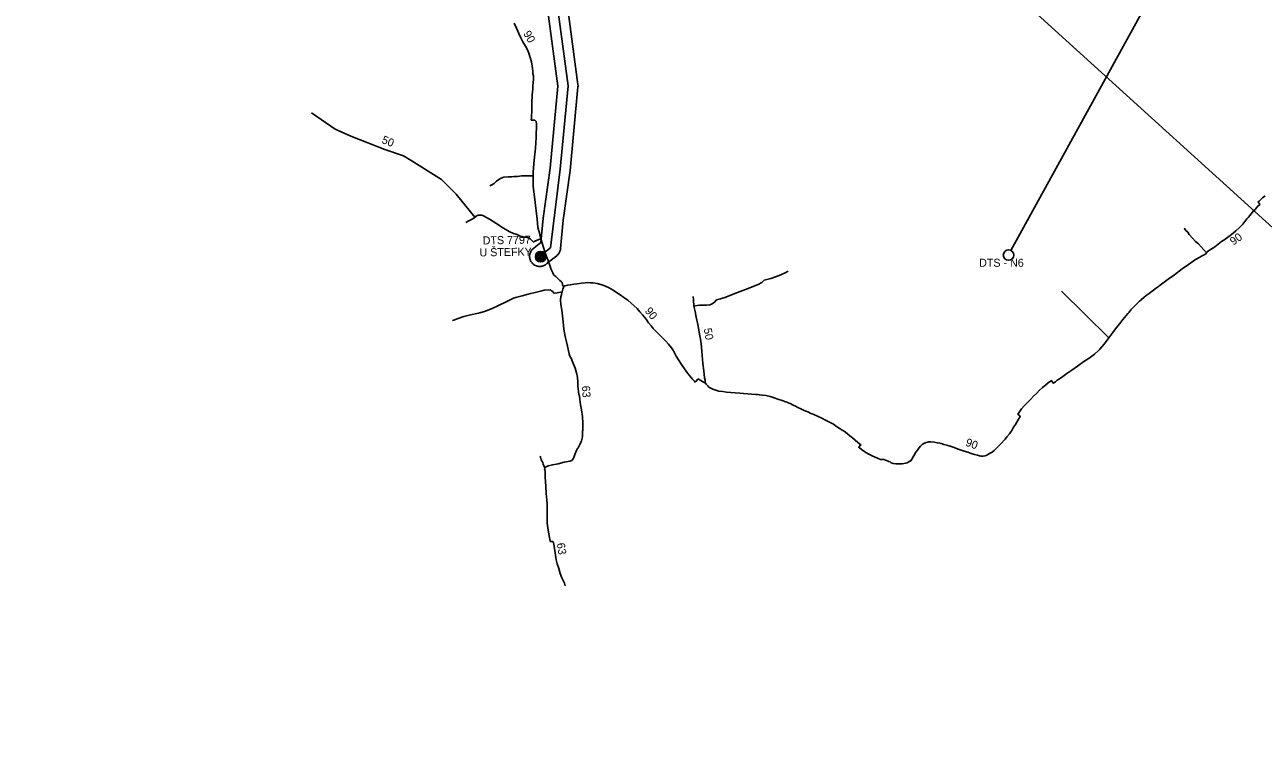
# Model space of a CAD drawing. Extents: x -444817 to -434929, y -1145681 to -1129851.
# Drawn here: x -443163 to -441925, y -1132491 to -1131768 of the extents above; entities that cross this region are included whole.
import ezdxf

# ---------------------------------------------------------------- set-up
doc = ezdxf.new("R2010")
doc.units = 0
for name, color, linetype in [('Vrstva 10', 7, 'Continuous'), ('Vrstva 11', 7, 'Continuous'), ('Vrstva 13', 7, 'Continuous'), ('Vrstva 15', 7, 'Continuous'), ('Vrstva 18', 7, 'Continuous'), ('Vrstva 19', 7, 'Continuous'), ('Vrstva 21', 7, 'Continuous'), ('Vrstva 27', 7, 'Continuous'), ('Vrstva 30', 7, 'Continuous'), ('Vrstva 35', 7, 'Continuous'), ('Vrstva 38', 7, 'Continuous'), ('Vrstva 59', 7, 'Continuous')]:
    doc.layers.add(name, color=color, linetype=linetype)

msp = doc.modelspace()

# ---------------------------------------------------------------- linework, layer by layer
at = {"layer": 'Vrstva 10'}
msp.add_lwpolyline([(-442969.9, -1131277.8), (-442709.6, -1131554.8), (-442646.1, -1131623.3), (-442636, -1131708.2), (-442619.8, -1131829.5), (-442627.8, -1131912.8), (-442637.3, -1131991.2), (-442648.1, -1131999.5)], dxfattribs=at)
at = {"layer": 'Vrstva 11'}
for radius in [5.25, 4.55, 3.85, 3.15, 2.45, 1.75, 1.05, 0.35]:
    msp.add_circle((-442647.2, -1132000.1), radius, dxfattribs=at)
at = {"layer": 'Vrstva 15'}
msp.add_lwpolyline([(-442645.9, -1131709.5), (-442629.9, -1131829.7), (-442637.7, -1131911.6), (-442644.7, -1131961.5), (-442646.9, -1131986), (-442650.3, -1131988.7), (-442652, -1131990), (-442654.5, -1131991.9), (-442655.4, -1131992.7), (-442655.9, -1131993.3), (-442656.6, -1131994.3), (-442657, -1131994.8), (-442657.5, -1131996), (-442657.8, -1131996.6), (-442658, -1131997.2), (-442658.1, -1131997.9), (-442658.3, -1131999.2), (-442658.3, -1132000.5), (-442658.2, -1132001.1), (-442658.1, -1132001.8), (-442658, -1132002.4), (-442657.8, -1132003), (-442657.5, -1132003.6), (-442657.3, -1132004.2), (-442657, -1132004.8), (-442656.6, -1132005.4), (-442656.2, -1132005.9), (-442655.8, -1132006.4), (-442655.4, -1132006.9), (-442654.9, -1132007.3), (-442654.4, -1132007.7), (-442653.9, -1132008.1), (-442653.3, -1132008.5), (-442652.8, -1132008.7), (-442652.5, -1132008.9), (-442651.9, -1132009.2), (-442651.3, -1132009.4), (-442650.7, -1132009.6), (-442650, -1132009.7), (-442649.4, -1132009.8), (-442648.9, -1132009.9), (-442648.7, -1132009.9), (-442648.1, -1132009.9), (-442647.4, -1132009.9), (-442646.9, -1132009.9), (-442646.8, -1132009.8), (-442646.1, -1132009.7), (-442645.5, -1132009.6), (-442644.9, -1132009.4), (-442644.2, -1132009.2), (-442643.6, -1132008.9), (-442643.1, -1132008.6), (-442642.5, -1132008.2), (-442642, -1132007.9), (-442641.5, -1132007.4), (-442641, -1132007), (-442640.5, -1132006.5), (-442640.4, -1132006.3), (-442631.2, -1131999.1), (-442630.7, -1131998.7), (-442630.3, -1131998.3), (-442629.8, -1131997.8), (-442629.4, -1131997.3), (-442629, -1131996.8), (-442628.7, -1131996.2), (-442628.4, -1131995.6), (-442628.1, -1131995), (-442627.9, -1131994.4), (-442627.7, -1131993.8), (-442627.5, -1131993.2), (-442627.4, -1131992.5), (-442627.4, -1131992.1), (-442624.8, -1131963.6), (-442617.8, -1131914.2), (-442609.9, -1131830.4), (-442609.8, -1131829.5), (-442609.9, -1131828.1), (-442626.1, -1131707)], dxfattribs=at)
at = {"layer": 'Vrstva 18'}
msp.add_line((-441963.4, -1131605.7), (-442177.2, -1131993.9), dxfattribs=at)
at = {"layer": 'Vrstva 19'}
msp.add_circle((-442179.6, -1131998.5), 5.25, dxfattribs=at)
at = {"layer": 'Vrstva 27'}
for points in [[(-442673.8, -1131767), (-442671.5, -1131771.9), (-442669.9, -1131775), (-442669, -1131777.1), (-442667, -1131781.5), (-442666.6, -1131782.3), (-442665, -1131785.5), (-442662.4, -1131789.9), (-442660.5, -1131793.6), (-442659.1, -1131796.9), (-442657.7, -1131801.1), (-442656.5, -1131805.5), (-442655.7, -1131809.8), (-442655, -1131814.6), (-442655, -1131817.5), (-442654.5, -1131819.5), (-442654.5, -1131822.3), (-442654.6, -1131826.8), (-442654.9, -1131829.1), (-442655.2, -1131832.5), (-442655.6, -1131838.5), (-442656.1, -1131846.7), (-442656.2, -1131852.9), (-442656.4, -1131861.3), (-442656.7, -1131863.7), (-442656.2, -1131863.7), (-442653.7, -1131863.6), (-442653.2, -1131863.7), (-442652.8, -1131864.1), (-442651.7, -1131865.2), (-442651.5, -1131867.5), (-442651.7, -1131881), (-442652.5, -1131891.7), (-442653.6, -1131903.8), (-442654.8, -1131915.3), (-442654.7, -1131919.2)], [(-442698.1, -1131929.2), (-442696, -1131928.4), (-442693.7, -1131926.9), (-442691.2, -1131924.8), (-442689.1, -1131922.9), (-442686.7, -1131921.7), (-442684, -1131920.8), (-442679.8, -1131920.4), (-442676.1, -1131920.3), (-442674.1, -1131920.1)], [(-442654.7, -1131919.2), (-442660.3, -1131919.2), (-442662.2, -1131919.2), (-442666.5, -1131919.5), (-442670.4, -1131919.9), (-442674.1, -1131920.1)], [(-442654.7, -1131919.2), (-442654.6, -1131929.6), (-442652.8, -1131946.1), (-442650.8, -1131962.8), (-442649.9, -1131970.9), (-442648.4, -1131976.4), (-442647.6, -1131979.5), (-442646.9, -1131982.4)], [(-441981.7, -1131996.2), (-441981, -1131995.4), (-441977.8, -1131993.1), (-441974.4, -1131990.9), (-441973.5, -1131990.3), (-441968.6, -1131986.4), (-441966.7, -1131985.1), (-441965.1, -1131984), (-441964.5, -1131983.6), (-441959.4, -1131980), (-441955.2, -1131976.6), (-441952.3, -1131974.4), (-441949.4, -1131971.5), (-441947.6, -1131969.8), (-441945.6, -1131967.7), (-441943.6, -1131965), (-441941.3, -1131962.3), (-441939.9, -1131960.6), (-441938.5, -1131958.9), (-441934.7, -1131954.4), (-441932.9, -1131952.5), (-441931.2, -1131950.4), (-441928.5, -1131948), (-441930.3, -1131945.2), (-441929.1, -1131944.5), (-441926.8, -1131942.3), (-441925.7, -1131941.3), (-441923, -1131939.5)], [(-442722, -1131965.9), (-442719.7, -1131964.7), (-442715.1, -1131962.3), (-442710.7, -1131959), (-442709.5, -1131958.7), (-442708.2, -1131958.5), (-442706.1, -1131958.7), (-442704.4, -1131959.2), (-442698.3, -1131962.7), (-442692, -1131966.8), (-442684.4, -1131971.7), (-442678.8, -1131975.1), (-442674.2, -1131977.1), (-442670.8, -1131977.9), (-442666.1, -1131980.6)], [(-442646.9, -1131982.4), (-442648, -1131982.7), (-442652.5, -1131984.2), (-442653.7, -1131985), (-442654.4, -1131985.5), (-442654.7, -1131985.4), (-442655, -1131985.1), (-442656.1, -1131983.9), (-442657.3, -1131982.7), (-442657.8, -1131982.3), (-442658.5, -1131981.9), (-442659.6, -1131981.4), (-442660.7, -1131980.9), (-442662.1, -1131980.7), (-442663.4, -1131980.5), (-442664.6, -1131980.5), (-442665.4, -1131980.5), (-442666.1, -1131980.6)], [(-442646.9, -1131982.4), (-442644.4, -1131991.1), (-442642.6, -1131996.3), (-442641.3, -1132000)], [(-442004, -1131971.6), (-442003.9, -1131971.8), (-442002.4, -1131973.9), (-442000.5, -1131975.7), (-441999, -1131978), (-441995.7, -1131981.5), (-441992.6, -1131984.9), (-441989.9, -1131987.3), (-441984.4, -1131993.2), (-441981.7, -1131996.2)], [(-441987.4, -1132000), (-441983.3, -1131997.8), (-441982.2, -1131996.8), (-441981.7, -1131996.2)], [(-442641.3, -1132000), (-442639.8, -1132004), (-442637.3, -1132010.8), (-442636.4, -1132013.7), (-442635.2, -1132016.3), (-442634.1, -1132018.5), (-442632.2, -1132019.9), (-442630.3, -1132021.6), (-442628, -1132023.8), (-442626.4, -1132025.2), (-442625.8, -1132026), (-442624.9, -1132029.5), (-442623.7, -1132029.4)], [(-442238, -1132189.5), (-442233.9, -1132190.8), (-442229.8, -1132192.3), (-442224, -1132194.2), (-442220.2, -1132195.5), (-442216.9, -1132196.6), (-442213.6, -1132197.7), (-442210.7, -1132198.5), (-442208.7, -1132199), (-442207, -1132199.4), (-442205.1, -1132199.4), (-442202.9, -1132199), (-442201.3, -1132198.3), (-442198.5, -1132196.8), (-442196.1, -1132195.2), (-442194, -1132193.6), (-442187.7, -1132187.3), (-442183.1, -1132182.3), (-442181.2, -1132179.9), (-442178.7, -1132177), (-442177.3, -1132175), (-442176.3, -1132173.7), (-442174.5, -1132170.5), (-442172.7, -1132167.6), (-442169.8, -1132162.5), (-442168, -1132159.6), (-442168.4, -1132159.1), (-442170.1, -1132157.9), (-442170.4, -1132157.4), (-442168.7, -1132155.1), (-442166.5, -1132152.2), (-442163.9, -1132149.2), (-442160.8, -1132145.9), (-442157.8, -1132142.8), (-442154.7, -1132139.4), (-442151.5, -1132136.4), (-442148.6, -1132133.4), (-442145.8, -1132130.9), (-442142.8, -1132128.4), (-442139.9, -1132126.1), (-442136.7, -1132123.8), (-442136.5, -1132124), (-442135.2, -1132126.1), (-442134.8, -1132126.4), (-442133.3, -1132125.5), (-442132.8, -1132125.1), (-442130.9, -1132123.5), (-442128.8, -1132122.2), (-442127.6, -1132121.4), (-442123.9, -1132118.7), (-442121.2, -1132116.7), (-442116.4, -1132113.3), (-442110.7, -1132109.4), (-442104.3, -1132104.8), (-442099.2, -1132101.5), (-442093.7, -1132097.4), (-442089.7, -1132093.9), (-442089.7, -1132093.8), (-442088.5, -1132092.6), (-442086.4, -1132090.2), (-442083.2, -1132086.1), (-442079.5, -1132081.3), (-442075.3, -1132075.9), (-442071.7, -1132070.9), (-442068.5, -1132066.7), (-442065.3, -1132062.7), (-442061.9, -1132058.8), (-442060.5, -1132057), (-442059.2, -1132055.4), (-442057.4, -1132053.3), (-442054.3, -1132050.1), (-442051.8, -1132047.6), (-442049.8, -1132045.7), (-442048.7, -1132044.7), (-442047.2, -1132043.1), (-442044.5, -1132040.8), (-442042.1, -1132038.9), (-442039.1, -1132036.8), (-442031.9, -1132031.3), (-442029.9, -1132029.9), (-442028.2, -1132028.7), (-442025.3, -1132026.5), (-442020.1, -1132022.7), (-442013.9, -1132018.3), (-442006, -1132012.4), (-441999.6, -1132007.8), (-441992.7, -1132003), (-441988.5, -1132000.6), (-441987.4, -1132000)], [(-442399.8, -1132014.7), (-442402.9, -1132016.2), (-442407.3, -1132018.2), (-442412.4, -1132020.2), (-442417.3, -1132021.8), (-442423.8, -1132023.6), (-442426.3, -1132025.9), (-442430, -1132027.9), (-442442.4, -1132032.8), (-442453, -1132036.9), (-442462.1, -1132040.4), (-442467.6, -1132042.1), (-442471.6, -1132043.3), (-442473.4, -1132045.6), (-442475.8, -1132047.3), (-442478.3, -1132048.3), (-442481.6, -1132048.6), (-442488.2, -1132048.4), (-442490.9, -1132049), (-442494.1, -1132049.4)], [(-442625.8, -1132035.3), (-442627.5, -1132035.7), (-442630.6, -1132036.1), (-442633.3, -1132036.4), (-442633.9, -1132036.4), (-442634.4, -1132036.1), (-442635.2, -1132035), (-442636.3, -1132034.2), (-442637.3, -1132033.2), (-442643.7, -1132033.6), (-442646.2, -1132034.2), (-442651.4, -1132035.6), (-442659.8, -1132037.7), (-442665.6, -1132039.3), (-442671, -1132040.7)], [(-442623.7, -1132029.4), (-442624.4, -1132030.9), (-442625.2, -1132032.7), (-442625.5, -1132033.9), (-442625.8, -1132035.3)], [(-442500, -1132116.8), (-442501.1, -1132115.3), (-442503.5, -1132112), (-442506.4, -1132107.7), (-442509.4, -1132103.3), (-442511.7, -1132099.4), (-442514.3, -1132094.3), (-442516.4, -1132091.3), (-442519.6, -1132087.5), (-442522, -1132084.5), (-442525.4, -1132081.1), (-442527.7, -1132078.8), (-442530.7, -1132075.9), (-442534.7, -1132071.8), (-442536.9, -1132069.2), (-442539.4, -1132066.1), (-442541.8, -1132062.6), (-442545.4, -1132058.2), (-442548, -1132055.1), (-442550.9, -1132051.8), (-442553.6, -1132049.1), (-442556.6, -1132046.5), (-442560.2, -1132043.5), (-442564.2, -1132040.8), (-442567.9, -1132038.2), (-442571.3, -1132035.8), (-442574.6, -1132033.6), (-442579.5, -1132030.9), (-442584, -1132028.9), (-442587.2, -1132027.8), (-442590.9, -1132026.9), (-442595, -1132026.3), (-442597.7, -1132026.1), (-442600, -1132026), (-442602.8, -1132026.3), (-442606.4, -1132026.5), (-442610.7, -1132027.1), (-442614.2, -1132027.6), (-442617.5, -1132028.1), (-442620.3, -1132028.7), (-442622.9, -1132029.2), (-442623.7, -1132029.4)], [(-442671, -1132040.7), (-442674.2, -1132041.7), (-442677.6, -1132043.2), (-442682.4, -1132045.4), (-442688.7, -1132048.4), (-442695.7, -1132051.8), (-442703.3, -1132054.9), (-442709.4, -1132056.6), (-442717.2, -1132058.3), (-442724, -1132060), (-442730.5, -1132062.1), (-442733.9, -1132063.6), (-442735.2, -1132063.8)], [(-442625.8, -1132035.3), (-442625.9, -1132036), (-442626.4, -1132038.1), (-442627, -1132040.3), (-442627.5, -1132043.1), (-442627, -1132047.9), (-442625.9, -1132053.4), (-442625.3, -1132059.2), (-442624.8, -1132065.3), (-442623.9, -1132072.6), (-442622.6, -1132080), (-442621.5, -1132085.1), (-442620.5, -1132089.6), (-442619.3, -1132094.3), (-442618.7, -1132097), (-442617.9, -1132099.4), (-442616.7, -1132101.4), (-442614.9, -1132105.8), (-442612.8, -1132111.3), (-442611.3, -1132116.1), (-442610.3, -1132120.7), (-442610.2, -1132125), (-442609.9, -1132129.6), (-442609.5, -1132134.9), (-442609.1, -1132137.6), (-442608.5, -1132139.1), (-442608.2, -1132142.6), (-442607.3, -1132148.2), (-442606.5, -1132153.2), (-442605.3, -1132159.9), (-442604.9, -1132166.4), (-442605.1, -1132173.4), (-442605.3, -1132174.5), (-442605.5, -1132176.2), (-442605.5, -1132177.9), (-442605.5, -1132180.2), (-442606.5, -1132184.1), (-442607.9, -1132187.6), (-442609.8, -1132191), (-442610.4, -1132191.8), (-442611.5, -1132193.8), (-442613.1, -1132197.7), (-442614.2, -1132200.7), (-442614.9, -1132202.2), (-442615.6, -1132203.2), (-442616.2, -1132203.7), (-442618, -1132204.2), (-442623.8, -1132205.5), (-442629.6, -1132207), (-442635.1, -1132207.9), (-442639.7, -1132209.1), (-442641.7, -1132209.9), (-442642.8, -1132210.7), (-442643.2, -1132211.3)], [(-442494.9, -1132039.9), (-442494.6, -1132043.3), (-442494.1, -1132049.4), (-442492.9, -1132054.8), (-442491.9, -1132060.6), (-442490.1, -1132068), (-442488.8, -1132075.4), (-442487.2, -1132084.4), (-442486.4, -1132090.6), (-442485.8, -1132098.9), (-442485.3, -1132106.9), (-442484.3, -1132114), (-442483.4, -1132121.1), (-442482.9, -1132123.6), (-442482.7, -1132126.4)], [(-442482.7, -1132126.4), (-442483, -1132126.2), (-442487.8, -1132123.6), (-442489.8, -1132122.2), (-442490.2, -1132122.5), (-442492.3, -1132124.7), (-442492.9, -1132125.3), (-442493.5, -1132124.4), (-442495.7, -1132122.2), (-442498.5, -1132118.7), (-442500, -1132116.8)], [(-442482.7, -1132126.4), (-442482.6, -1132126.5), (-442481.8, -1132127.4), (-442480.2, -1132129), (-442479, -1132130.3), (-442477.1, -1132131.5), (-442475.1, -1132132.4), (-442472.3, -1132133.3), (-442469, -1132134.3), (-442465.2, -1132134.9), (-442461.5, -1132135.3), (-442457.1, -1132135.9), (-442452.9, -1132136.2), (-442448.3, -1132136.5), (-442444.4, -1132136.9), (-442440.3, -1132137.2), (-442436.6, -1132137.5), (-442432.1, -1132137.8), (-442430.2, -1132137.7), (-442428.6, -1132138.1), (-442425.5, -1132138.5), (-442422.3, -1132138.9), (-442417.7, -1132139.9), (-442413.7, -1132141.1), (-442410.1, -1132142.3), (-442405.7, -1132143.8), (-442402.2, -1132145.2), (-442397.9, -1132146.9), (-442394.8, -1132148.3), (-442392.6, -1132149.5), (-442390.1, -1132150.7), (-442387.2, -1132152.2), (-442384, -1132153.6), (-442380.2, -1132155.2), (-442377.1, -1132156.6), (-442376, -1132157.1), (-442374.2, -1132157.9), (-442370.4, -1132159.5), (-442366.3, -1132161.4), (-442362.4, -1132163.3), (-442358.5, -1132165.3), (-442354.7, -1132167.5), (-442351.5, -1132169.8), (-442348, -1132171.9), (-442345.1, -1132173.8), (-442343, -1132175.2), (-442342.6, -1132175.5), (-442340.7, -1132177), (-442338.2, -1132179), (-442335.7, -1132181.1), (-442332.9, -1132183.4), (-442330.2, -1132185.8), (-442327.2, -1132188.2), (-442327.5, -1132188.3), (-442329.1, -1132190.3), (-442329.3, -1132190.5), (-442326.6, -1132192.6), (-442323.3, -1132194.9), (-442319.9, -1132197), (-442315.1, -1132199.4), (-442310.5, -1132201.5), (-442307.6, -1132202.7), (-442306, -1132202.6), (-442305.2, -1132202.5), (-442301.7, -1132203.7), (-442299.1, -1132204.6), (-442298, -1132205.1), (-442296.9, -1132205.9), (-442294.8, -1132206.7), (-442292.2, -1132207), (-442290.6, -1132207), (-442289.9, -1132206.9), (-442287.4, -1132206.9), (-442285.9, -1132206.9), (-442284.3, -1132206.8), (-442282.4, -1132206.2), (-442281, -1132205.9), (-442278.2, -1132204.5), (-442277.8, -1132204.2), (-442277.3, -1132203.9), (-442276.2, -1132202.4), (-442274.8, -1132200), (-442273.7, -1132198), (-442272.8, -1132196.4), (-442272.1, -1132195.2), (-442270.7, -1132193.3), (-442269.2, -1132191.2), (-442267.7, -1132189.3), (-442266, -1132187.6), (-442264.2, -1132186.6), (-442262.1, -1132185.7), (-442260.3, -1132185.3), (-442259.5, -1132185.2), (-442257.2, -1132185.1), (-442254.1, -1132185.5), (-442250.8, -1132185.9), (-442248.2, -1132186.4), (-442246.9, -1132186.7), (-442244.4, -1132187.6), (-442241.4, -1132188.5), (-442238, -1132189.5)], [(-442647.8, -1132199.2), (-442647.5, -1132200.2), (-442646.6, -1132203), (-442645.2, -1132205.8), (-442644.7, -1132207.6), (-442643.8, -1132209.4), (-442643.2, -1132211.3)], [(-442643.2, -1132211.3), (-442643.3, -1132211.9), (-442643.2, -1132212.9), (-442642.8, -1132214.8), (-442642.6, -1132220.1), (-442642.1, -1132229.8), (-442641.6, -1132236.6), (-442641, -1132243.3), (-442640.8, -1132246.8), (-442640.7, -1132256.3), (-442640.8, -1132260.6), (-442640.6, -1132266.2), (-442639.6, -1132273.4), (-442639, -1132277), (-442637.8, -1132284.2), (-442637.7, -1132284.5), (-442637.3, -1132284.7), (-442635.1, -1132284.6), (-442634.8, -1132284.8), (-442634.6, -1132285.1), (-442634.5, -1132285.8), (-442634.1, -1132287.3), (-442632.8, -1132295.8), (-442631.6, -1132302.8), (-442630.6, -1132306.9), (-442629.2, -1132311.7), (-442627.6, -1132316.4), (-442625.9, -1132320.9), (-442623.5, -1132326.2), (-442622.7, -1132328.7)]]:
    msp.add_lwpolyline(points, dxfattribs=at)
at = {"layer": 'Vrstva 35'}
msp.add_line((-442079.5, -1132081.3), (-442126.8, -1132034.5), dxfattribs=at)
msp.add_lwpolyline([(-442876.4, -1131856.5), (-442852.7, -1131872.8), (-442837, -1131879.9), (-442802.9, -1131893.2), (-442784.3, -1131899.5), (-442776.6, -1131903.9), (-442746.4, -1131922.9), (-442731.6, -1131937.7), (-442713.1, -1131960.8)], dxfattribs=at)
at = {"layer": 'Vrstva 59'}
msp.add_lwpolyline([(-443357.8, -1130664.3), (-442622.2, -1131330.9), (-441886.7, -1131997.4), (-441341.9, -1132491)], dxfattribs=at)

# ---------------------------------------------------------------- texts
at = {"layer": 'Vrstva 13'}
for s, p in [('DTS 7797', (-442705.1, -1131987.9)), ('U ŠTEFKY', (-442708.3, -1131999.9))]:
    msp.add_text(s, height=8, rotation=1, dxfattribs=at).set_placement(p)
at = {"layer": 'Vrstva 21'}
msp.add_text('DTS - N6', height=8, dxfattribs=at).set_placement((-442209, -1132010.2))
msp.add_text('DTS - N6', height=8, dxfattribs=at).set_placement((-442209, -1132010.2))
at = {"layer": 'Vrstva 30'}
for s, rotation, p in [('90', 300.023, (-442664.9, -1131777.2)), ('90', 35.0146, (-441954.9, -1131989.1)), ('90', 308.8337, (-442543.6, -1132054.5)), ('50', 280.0369, (-442484.3, -1132072.1)), ('63', 273.8059, (-442606, -1132129.2)), ('90', 340.495, (-442223.2, -1132188.7)), ('63', 278.9796, (-442631.1, -1132286.5))]:
    msp.add_text(s, height=8, rotation=rotation, dxfattribs=at).set_placement(p)
at = {"layer": 'Vrstva 38'}
msp.add_text('50', height=8, rotation=338.6294, dxfattribs=at).set_placement((-442806.7, -1131886.4))

doc.saveas('drawing.dxf')
